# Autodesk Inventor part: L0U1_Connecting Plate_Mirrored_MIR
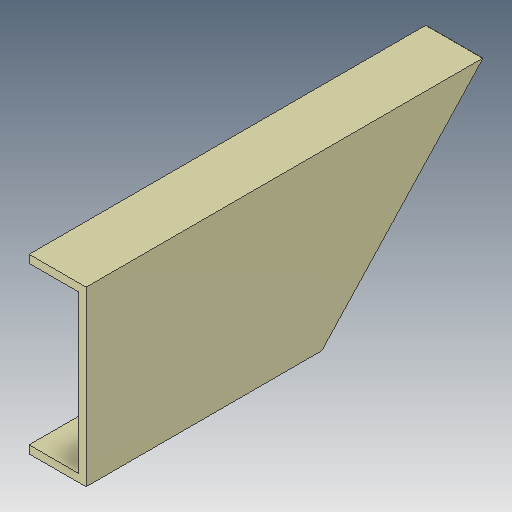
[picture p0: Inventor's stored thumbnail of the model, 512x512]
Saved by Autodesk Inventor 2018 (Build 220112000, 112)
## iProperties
Created: 2018-02
Part Number: L0U1_Connecting Plate_Mirrored_MIR
Material: Steel, Mild
Document SubType Name: Modeling
Designer: STK
Density: 7.85 g/cm^3
Appearance: Semi-Polished
Author: STK
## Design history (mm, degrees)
derived "L0U1_Connecting Plate_Mirrored.ipt"
feature "Solid1::L0U1_Connecting Plate_Mirrored.ipt" dims "d0" = 10
tag "TaggingFeature1"
body "Solid1"
